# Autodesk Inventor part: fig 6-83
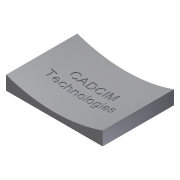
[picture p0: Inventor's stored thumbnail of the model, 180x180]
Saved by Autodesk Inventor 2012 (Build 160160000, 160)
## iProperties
Shininess: 64.0
Length Units: 11269
Angle Units: 11279
Time Units: 11290
Mass Units: 11283
Length Display Precision: 3
Angle Display Precision: 2
Compacted: True
Part Number: fig 6-83
Document SubType Name: Modeling
Created: 2002-12
Designer: deepak
Density: 1 g/cm^3
Material: Default
Density: 0.0
Volumn: 0.0
Area: 0.0
PropertySet Name: Model Information
Control State: 0
Master: False
Checked Out: False
Author: deepak
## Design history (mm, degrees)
sketch "Sketch1"
  geometry: L1 (-39.922, 33.786)-(30.103, 33.786); L2 (30.103, 33.786)-(30.103, -17.894); L3 (30.103, -17.894)-(-39.922, -17.894); L4 (-39.922, -17.894)-(-39.922, 33.786)
  constraints: 8 end point, 2 parallel, 1 horizontal, 1 perpendicular
extrude "Extrusion1" new body sketch "Sketch1" distance "d0" = 10; taper "d1" = 0 deg
workplane "Work Plane1"
sketch "Sketch2"
  geometry: L1 (-37.656, 15.034)-(26.28, 15.034); L2 (26.28, 15.034)-(26.28, 10.168); L3 (26.28, 10.168)-(-37.656, 10.168); L4 (-37.656, 10.168)-(-37.656, 15.034)
  constraints: 2 other
sketch "Sketch3"
  geometry: L1 (70.026, 10)-(0, 10) reference; A1 r 105 centre (35.013, 108.99) between (0, 10) and (70.026, 10)
  constraints: 2 point on circle, 1 centre point
  dimensions: "d5" = 105 radius of A1
extrude "Extrusion2" cut sketch "Sketch3" stored distance "d3" = 10; taper "d4" = 0 deg
emboss "Emboss4" sketch "Sketch2" dims "d14" = 1, "d15" = 0
body "Solid1"
other parameters: "d2" = 5
